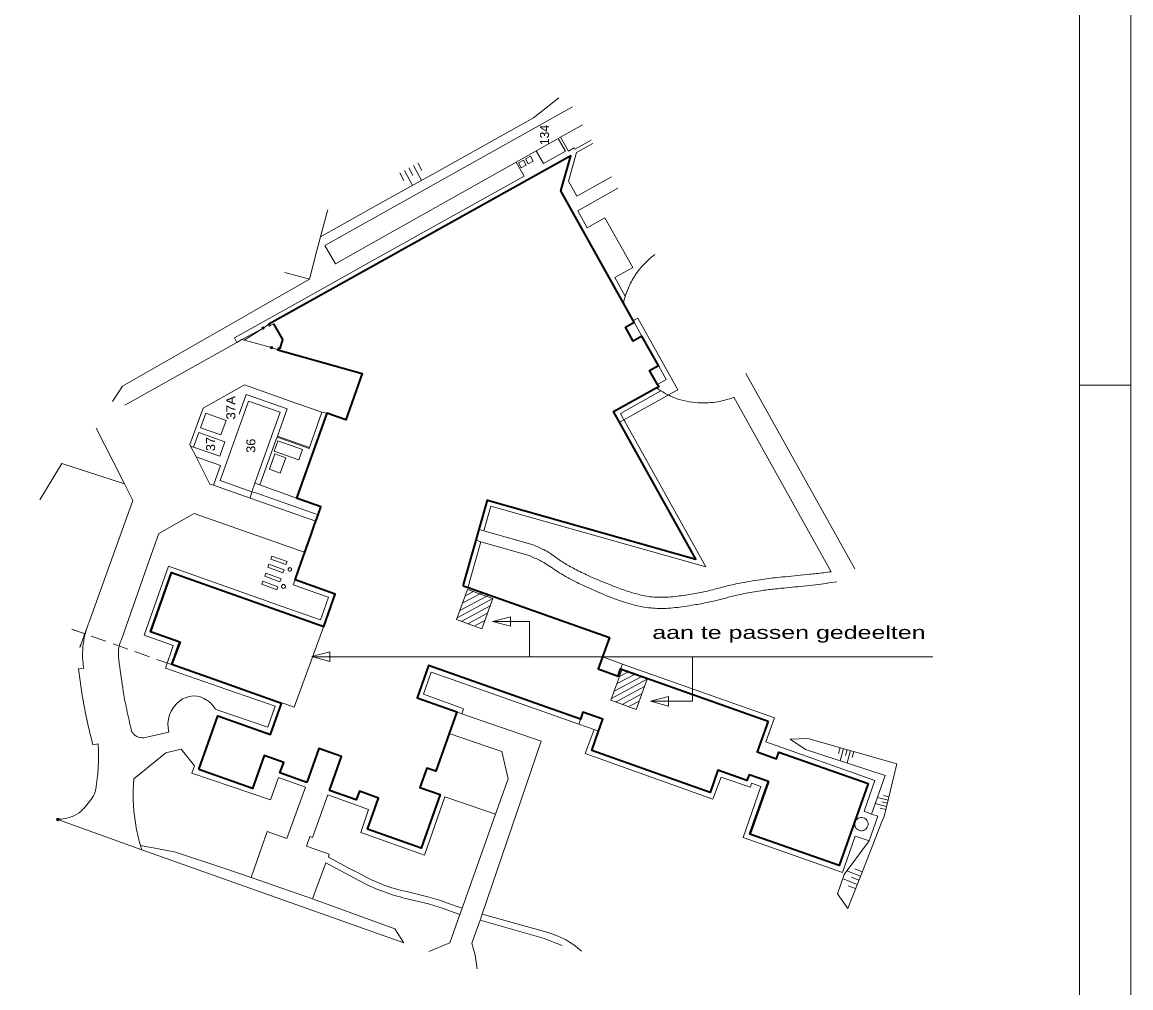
# Model space of a CAD drawing. Extents: x 295824 to 414724, y 24924 to 109024.
# Drawn here: x 393186 to 414724, y 42915 to 61673 of the extents above; entities that cross this region are included whole.
import ezdxf

# ---------------------------------------------------------------- set-up
doc = ezdxf.new("R2010")
doc.units = 0
doc.header["$LTSCALE"] = 100
doc.header["$PDMODE"] = 32
doc.header["$PDSIZE"] = 50
doc.linetypes.add('MEDIUM_DASHED', pattern=[4.5, 3, -1.5])
for name, color, linetype, lineweight in [('1', 7, 'Continuous', 13), ('16', 7, 'Continuous', 13), ('19', 7, 'Continuous', 13), ('20', 7, 'Continuous', 13), ('22', 7, 'Continuous', 13), ('25', 7, 'Continuous', 13), ('26', 7, 'Continuous', 13), ('32', 7, 'Continuous', 13), ('4', 7, 'Continuous', 35), ('40', 7, 'Continuous', 13), ('51', 7, 'Continuous', 13), ('52', 7, 'Continuous', 13), ('58', 7, 'Continuous', 35), ('62', 7, 'Continuous', 13)]:
    doc.layers.add(name, color=color, linetype=linetype, lineweight=lineweight)
doc.layers.add('57', color=7, linetype='Continuous')

msp = doc.modelspace()

# ---------------------------------------------------------------- linework, layer by layer
at = {"layer": '1'}
for p, q in [((414723.6, 24923.8), (414723.6, 109023.8)), ((413723.6, 54623.8), (414723.6, 54623.8))]:
    msp.add_line(p, q, dxfattribs=at)
msp.add_lwpolyline([(304995.6, 25923.8), (413723.6, 25923.8), (413723.6, 108023.8), (304995.6, 108023.8)], dxfattribs=at)
at = {"layer": '16'}
for p, q in [((401637.8, 50104.4), (402329.8, 50474.7)), ((401688.7, 50245), (402224.2, 50531.6)), ((401749.3, 50390.9), (402107.4, 50582.5)), ((401790.5, 50526.4), (401951.6, 50612.6)), ((401716.4, 50033.1), (402278.9, 50334.1)), ((401842.9, 49987.3), (402228, 50193.4)), ((401985.2, 49950), (402177.1, 50052.7)), ((402325.2, 50031.1), (403042.9, 50031.1)), ((403042.9, 49347.6), (403042.9, 50031.1)), ((398842.4, 49347.6), (410879.7, 49347.6)), ((404635.9, 48537.7), (405328, 48908.1)), ((404686.8, 48678.4), (405222.3, 48965)), ((404747.4, 48824.2), (405105.5, 49015.9)), ((404788.7, 48959.8), (404949.7, 49046)), ((404714.6, 48466.4), (405277, 48767.5)), ((404841, 48420.7), (405226.1, 48626.8)), ((404983.3, 48383.4), (405175.2, 48486.1))]:
    msp.add_line(p, q, dxfattribs=at)
for points in [[(401624.1, 50066.5), (402117.4, 49887.9), (402330.1, 50475.6), (401836.8, 50654.2)], [(404622.2, 48499.8), (405115.6, 48321.3), (405328.3, 48909), (404834.9, 49087.5)]]:
    msp.add_lwpolyline(points, close=True, dxfattribs=at)
msp.add_lwpolyline([(405390, 48481.1), (406207.6, 48481.1), (406207.6, 49347.6)], dxfattribs=at)
at = {"layer": '19'}
for p, q in [((397994.5, 55771.6), (398071, 55814.3)), ((398557.8, 53171.3), (398081.3, 53341.3)), ((398306.2, 53210.1), (398096.2, 53285)), ((398306.2, 53210.1), (398200.4, 52913.4)), ((398630, 53373.5), (398557.8, 53171.3)), ((398200.4, 52913.4), (397990.4, 52988.3)), ((407676.2, 48097.5), (404812.8, 49109.8))]:
    msp.add_line(p, q, dxfattribs=at)
for points in [[(403601.4, 59412.8), (403740.2, 59164.2), (403312.4, 58925.3), (403174.2, 59172.8)], [(403114.5, 58972.2), (403017.5, 58918), (402963.4, 59015), (403060.3, 59069.1)], [(402879.6, 58841), (402976.5, 58895.1), (402922.4, 58992), (402825.5, 58937.9)], [(397648.7, 52551), (397032.6, 52768.7), (397583.1, 54313.8), (398195.4, 54096.9), (397707.6, 52717.5)], [(396751.7, 54077.9), (397147.3, 53937), (397046.6, 53654.4), (396651, 53795.3)], [(397023.3, 53240.1), (397123.3, 53520.9), (396617.4, 53701.1), (396517.4, 53420.4)]]:
    msp.add_lwpolyline(points, close=True, dxfattribs=at)
for points in [[(398630, 53373.5), (398152.8, 53541.8), (398081.3, 53341.3)], [(404384.6, 47900.8), (404250.2, 47523.7), (406548.4, 46709)], [(407323.4, 45901.1), (409057.7, 45288.3), (409621.6, 46881.2)]]:
    msp.add_lwpolyline(points, dxfattribs=at)
at = {"layer": '20'}
msp.add_lwpolyline([(396651, 53795.3), (396751.7, 54077.9), (397147.3, 53937), (397046.6, 53654.4)], close=True, dxfattribs=at)
at = {"layer": '22'}
for p, q in [((397864.6, 55731.3), (397977.2, 55803.4)), ((398027.4, 55350.8), (398153.7, 55306.1)), ((398096.2, 53285), (397990.4, 52988.3))]:
    msp.add_line(p, q, dxfattribs=at)
msp.add_lwpolyline([(404790.2, 53904), (404875.3, 53951.3), (405720, 54420.6), (405739.4, 54431.4), (405921.5, 54532.6), (405147.5, 55925.7), (405057.3, 55875.6)], dxfattribs=at)
at = {"layer": '25'}
msp.add_line((409952.4, 47041.8), (409686.3, 46291.6), dxfattribs=at)
for points in [[(403610.8, 60200), (403118.7, 59814.1), (402208.5, 59305.7), (401220.8, 58754.1), (400066, 58109), (399351.9, 57710.2), (398982.8, 57504)], [(398764.9, 56679.7), (395135.1, 54600), (394939.9, 54301.2)], [(395172.3, 52704.7), (394697.8, 52857.8), (393957.3, 53096.8), (393527.8, 52393.7)], [(410181.1, 47264.9), (408451.4, 47760.6), (408105.6, 47746.2), (408403.1, 47546.5), (409952.4, 47041.8)], [(409641.4, 45769.8), (409154.8, 45117.9), (409022.6, 44737.9), (409225.8, 44458.1), (409599.6, 45406.7), (409883.1, 46125.9), (409930.4, 46245.8), (410181.1, 47264.9)]]:
    msp.add_lwpolyline(points, dxfattribs=at)
at = {"layer": '26'}
for p, q in [((400697.9, 58840.6), (400778, 58695.5)), ((400785.4, 58889), (400945, 58600)), ((400872.9, 58937.3), (400953.1, 58792.2)), ((400522.8, 58744), (400602.9, 58598.8)), ((400610.3, 58792.3), (400770.4, 58502.5)), ((409043, 47463.7), (409076.7, 47581.4)), ((409076.5, 47326.8), (409144, 47562.2)), ((409177.5, 47425.2), (409211.2, 47542.8)), ((409210.9, 47288.2), (409278.4, 47523.5)), ((409311.9, 47386.6), (409345.6, 47504.3)), ((409800.3, 46613), (410008.2, 46561.9)), ((409886.1, 46527.2), (409993.1, 46500.9)), ((409916.2, 46649.5), (410023.3, 46623.1)), ((409758, 46493.9), (409978, 46439.8)), ((409856, 46404.8), (409963, 46378.6)), ((409122.7, 45036), (409409, 44923.2)), ((409209.3, 45190.8), (409473.5, 45086.7)), ((409298.2, 45061.4), (409441.3, 45004.9)), ((409362.6, 45225), (409505.8, 45168.6)), ((409233.6, 44897.7), (409376.8, 44841.3))]:
    msp.add_line(p, q, dxfattribs=at)
at = {"layer": '32'}
for p in [(398039.3, 51301.9), (398309.4, 51135.5)]:
    msp.add_line(p, (398331.2, 51194.6), dxfattribs=at)
msp.add_lwpolyline([(398309.4, 51135.5), (398016.7, 51243.1), (398039.3, 51301.9)], dxfattribs=at)
for points in [[(397980.8, 51142.5), (397957.9, 51083.7), (398252.7, 50975.2), (398272.9, 51031.7)], [(398214.9, 50860.9), (398194.6, 50804.4), (397899.7, 50913), (397921.5, 50969.7)], [(397861.1, 50811.9), (397838.9, 50754.1), (398133.1, 50644.1), (398154.6, 50702.9)]]:
    msp.add_lwpolyline(points, close=True, dxfattribs=at)
for centre, radius, start, end in [((398414.3, 51048.8), 62.3, 174.88401, 210.92845), ((398401.9, 51024), 58.2, 110.85429, 148.54529), ((398383.6, 51038), 40.5, 38.66887, 93.52701), ((398377.3, 51045.9), 41.7, 337.95407, 24.52464), ((398386.5, 51053.6), 45, 235.11752, 280.94338), ((398381.1, 51044.4), 37.6, 291.80741, 337.95407), ((398262.2, 50712.3), 38.6, 160.33052, 203.06541), ((398262, 50712.3), 38.4, 113.54211, 160.33052), ((398262.2, 50712.3), 38.6, 203.06541, 245.79546), ((398262.6, 50712.1), 38.6, 245.06344, 293.39196), ((398262.2, 50711.8), 39, 67.13969, 113.54211), ((398262.2, 50711.8), 39, 24.60068, 67.13969), ((398262.6, 50712.1), 38.6, 293.39196, 341.72546), ((398262.8, 50712), 38.4, 341.72546, 24.60068)]:
    msp.add_arc(centre, radius, start, end, dxfattribs=at)
at = {"layer": '4', "lineweight": 13}
for p, q in [((394152.4, 49880.4), (394401.5, 49789.7)), ((394443.5, 49904.4), (394304.5, 49522.6))]:
    msp.add_line(p, q, dxfattribs=at)
at = {"layer": '4', "linetype": 'MEDIUM_DASHED', "lineweight": 13}
msp.add_line((396084.7, 49195.4), (394177.1, 49870.9), dxfattribs=at)
at = {"layer": '4'}
msp.add_line((407682.1, 46922.5), (407323.4, 45901.1), dxfattribs=at)
for points in [[(401755.5, 50725.4), (402004.7, 51607.9), (402063.4, 51815.8), (402225, 52388.3), (406270.1, 51244), (404790.2, 53904), (404676.4, 54108.5), (405505, 54568.9), (405551.2, 54594.6), (405528.8, 54634.6), (405375.9, 54908.1), (405545.3, 55002.8), (405227.1, 55571.9), (405057.8, 55477.2), (404906, 55748.7), (405075.4, 55843.3), (405057.3, 55875.6), (404867.5, 56215.2), (403647.8, 58397.1), (403847.2, 59075.1), (397977.2, 55803.4), (397994.5, 55771.6)], [(398071, 55814.3), (398242, 55507.9), (398193, 55333.5), (398163.7, 55341.7), (398153.7, 55306.1), (399789.2, 54845.9), (399472.2, 53947), (399104.7, 54076), (398516.9, 52428.8)], [(396620.6, 47155), (396988.7, 48197), (398011.6, 47835.6), (398224.4, 48439.3), (397208.2, 48799.4), (396092.4, 49194.8), (396246.1, 49628.8), (395679.9, 49831.6), (396089.4, 50984.3), (399043.4, 49934.9), (399266, 50561.5), (398487.7, 50838), (398558.6, 51047.4), (398675, 51375.3), (398791.6, 51703.9), (398866.3, 51915), (398888.5, 51977.7), (398933.2, 52104.6), (398986.9, 52261.1), (398516.9, 52428.8)], [(401755.5, 50725.4), (401848.4, 50692.5), (404592.8, 49719.5), (404459.2, 49342.8), (404378.4, 49109), (404763.5, 48970.3), (404812.8, 49109.8), (407676.2, 48097.5)], [(407840.9, 47364.6), (407885.5, 47494), (409621.6, 46881.2), (409057.7, 45288.3), (407323.4, 45901.1), (407682.1, 46922.5), (407306.7, 47054.4), (407266.2, 46939.4), (406701.7, 47141.6), (406548.4, 46709), (404250.2, 47523.7), (404384.6, 47900.8), (404467.2, 48132.8), (404078, 48271.3), (404029.4, 48133.6), (401076.5, 49176.1), (400857.1, 48550.4), (401629.1, 48277.2), (401481, 47858.5), (401220, 47121), (401046.4, 47179.6), (400911.6, 46809.4), (401307.5, 46669.3), (400938.1, 45625), (399894, 45994.6), (400109.5, 46600.3), (399736.5, 46733.1), (399676.5, 46564.6), (399153.3, 46750.8), (399387, 47407.1), (398951.8, 47561.8), (398718.4, 46905.2)], [(407676.2, 48097.5), (407463.1, 47497.9), (407840.9, 47364.6), (407885.5, 47494), (409621.6, 46881.2)], [(398718.4, 46905.2), (398194.3, 47091.4), (398266.1, 47294), (397889.1, 47427.5), (397662.3, 46786.5), (396620.6, 47155)]]:
    msp.add_lwpolyline(points, dxfattribs=at)
at = {"layer": '4', "lineweight": 13}
for centre, start, end in [((409489.7, 46095.1), 29.64, 208.17622), ((409488.7, 46097), 209.13476, 28.68146)]:
    msp.add_arc(centre, 130, start, end, dxfattribs=at)
at = {"layer": '40'}
for p, q in [((398764.9, 56679.7), (398286.4, 56808.8)), ((397864.6, 55731.3), (397454.8, 55506.7)), ((397495.8, 55495.5), (397864.6, 55731.3)), ((397495.8, 55495.5), (398027.4, 55350.8)), ((398138.2, 53614), (398145, 53632.8)), ((398766.5, 53411.1), (398145, 53632.8))]:
    msp.add_line(p, q, dxfattribs=at)
for points in [[(398764.9, 56679.7), (398911.9, 57235.7), (398982.8, 57504), (399103.3, 57960), (399121.5, 58029)], [(397454.8, 55506.7), (397495.8, 55495.5), (398027.4, 55350.8)], [(398766.5, 53411.1), (398759.8, 53392.2), (398138.2, 53614)]]:
    msp.add_lwpolyline(points, dxfattribs=at)
for p in [(397864.6, 55731.3), (398027.4, 55350.8)]:
    msp.add_point(p, dxfattribs=at)
at = {"layer": '51'}
for p, q in [((403957.9, 59142.6), (404273.2, 59318.6)), ((403799.9, 58585.5), (403957.9, 59142.6)), ((402936.5, 58681.6), (402784.5, 58953.9)), ((403962.2, 58293), (403799.9, 58585.5)), ((404636.2, 58666.8), (403962.2, 58293)), ((405047, 56907.9), (404700.3, 56714.1)), ((404903, 56351.5), (404700.3, 56714.1)), ((405075.4, 55843.3), (405227.1, 55571.9)), ((407244.8, 54850), (409362.2, 51051.9)), ((405594.3, 54510.1), (404809.2, 54069.8)), ((408900.9, 50997.6), (407012.5, 54386.6)), ((398334.9, 54159.7), (398145, 53632.8)), ((399010.6, 54094.7), (398766.5, 53411.1)), ((396517.4, 53420.4), (396458.6, 53438.4)), ((394482.1, 50007.5), (395335.4, 52381.9)), ((397612.8, 52424.6), (398888.5, 51977.7)), ((397727.4, 52532.7), (397648.7, 52551)), ((397727.4, 52532.7), (398933.2, 52104.6)), ((395837.9, 51740.3), (396526.8, 52127.6)), ((402157, 51789.4), (402291.7, 52271.2)), ((402291.7, 52271.2), (406469.1, 51093.1)), ((395553.3, 49767.1), (396029.2, 51104.4)), ((398453.6, 50744.1), (398487.7, 50838)), ((394381.4, 49123.5), (394281.5, 49111.4)), ((404848.9, 49204.6), (407802.1, 48162.4)), ((400982.3, 48621.9), (401131.9, 49048)), ((401131.9, 49048), (401542.2, 48903.6)), ((403999.3, 48038.2), (401542.2, 48903.6)), ((397957, 47975.5), (398099.6, 48385.3)), ((396037.1, 47883.5), (395551, 47773.5)), ((404295.5, 47932.6), (404121.5, 47464.7)), ((394560.4, 47633.9), (394659.7, 47657.5)), ((402123.7, 44344.8), (403266.3, 47703.7)), ((406766.5, 47010), (406661.6, 46732.2)), ((407121.4, 46884.6), (406766.5, 47010)), ((399766.3, 45934.4), (399917, 46376.6)), ((393877.2, 46186.4), (395511.3, 45595.9)), ((398706.7, 45668.9), (399149.3, 45509.8)), ((395511.3, 45595.9), (400600.1, 43786.2)), ((398823, 44643.2), (399084.9, 45339.8)), ((399084.9, 45339.8), (399837.2, 44941.7)), ((401063.5, 44682), (400650.8, 44783.7)), ((400693.3, 44640.4), (401078.9, 44544.3)), ((402123.7, 44344.8), (403381.5, 43993.6)), ((400422.4, 44061.7), (400600.1, 43786.2)), ((403305.5, 43878.6), (403676.6, 43740.2))]:
    msp.add_line(p, q, dxfattribs=at)
for points in [[(403878.2, 60027.9), (399066.9, 57331.8), (399269.8, 56979.7)], [(404073.2, 59677.8), (403645, 59437.3), (403601.4, 59412.8), (403174.2, 59172.8), (402784.5, 58953.9), (399958.2, 57366.4), (399269.8, 56979.7)], [(404238.1, 59381.5), (403923.2, 59205.7), (403910, 59229.3), (403796.5, 59165.9), (403645, 59437.3)], [(402936.5, 58681.6), (399915.1, 56994.9), (398879.3, 56416.7), (397309.5, 55540.4), (397359.4, 55453.3)], [(405047, 56907.9), (404502.1, 57871.9), (404161, 57678.1), (403977.8, 58011.1), (404759, 58446.2)], [(397454.8, 55506.7), (397359.4, 55453.3), (395179.9, 54235)], [(405528.8, 54634.6), (405698.5, 54728.7), (405545.3, 55002.8)], [(396458.6, 53438.4), (396445.5, 53466.9), (396701.9, 54177.1), (396850.4, 54259.9), (397504.7, 54624.9), (398390, 54313.2), (399010.6, 54094.7), (399104.7, 54076)], [(398334.9, 54159.7), (397538.2, 54437.2), (397403.4, 54061.5)], [(406469.1, 51093.1), (404889.6, 53925.7), (404875.3, 53951.3), (404809.2, 54069.8)], [(395335.4, 52381.9), (395172.3, 52704.7), (394960.8, 53123.1), (394624.3, 53789.1)], [(396564.7, 53229.8), (397039, 53059.1), (396902.9, 52676.3), (396833.7, 52701.2), (396564.7, 53229.8), (396458.6, 53438.4)], [(398138.2, 53614), (398116.8, 53554.6), (397802.8, 52683.6)], [(396902.9, 52676.3), (397612.8, 52424.6), (397648.7, 52551)], [(397707.6, 52717.5), (397802.8, 52683.6), (398103.7, 52576), (398198, 52542.6)], [(398198, 52542.6), (398427.2, 52460.8), (398516.9, 52428.8)], [(396526.8, 52127.6), (398576.5, 51409.8), (398675, 51375.3)], [(395837.9, 51740.3), (395660.9, 51237.6), (395106.4, 49662.6)], [(402063.4, 51815.8), (402157, 51789.4), (403113.3, 51518.6)], [(402097.2, 51581.4), (401878.4, 50799.6), (401848.4, 50692.5)], [(403008.7, 51321), (402097.2, 51581.4), (402004.7, 51607.9)], [(398982.6, 50062.5), (398682.3, 50168.4), (398347.9, 50286.4), (396029.2, 51104.4)], [(398453.6, 50744.1), (398511.3, 50723.6), (398892.3, 50588.1), (399138.3, 50500.7)], [(399138.3, 50500.7), (399046.4, 50241.9), (398982.6, 50062.5)], [(395553.3, 49767.1), (396120.9, 49567.9), (395967.6, 49127)], [(404812.8, 49109.8), (404848.9, 49204.6), (404553.5, 49310.5), (404459.2, 49342.8)], [(398099.6, 48385.3), (397165.1, 48710.4), (395967.6, 49127)], [(400982.3, 48621.9), (401622.2, 48385), (401659.3, 48371.2)], [(396940.1, 48325.3), (397026.8, 48295.5), (397957, 47975.5)], [(403266.3, 47703.7), (401730.1, 48237.9), (401759.4, 48334.1), (401659.3, 48371.2), (401622.2, 48385)], [(404029.4, 48133.6), (403999.3, 48038.2), (404295.5, 47932.6), (404384.6, 47900.8)], [(409752.5, 46942.3), (407635.3, 47691.3), (407802.1, 48162.4)], [(395355.6, 46971.7), (395978.2, 47478.2), (396272.2, 47549), (396531.4, 47225.7), (396485, 47087.4)], [(406661.6, 46732.2), (406604.8, 46581.9), (404121.5, 47464.7)], [(397124.2, 45235), (397637.2, 45061.2), (397947.5, 45954.5), (398328.1, 45813.6), (398687.2, 46815.1), (398164.9, 46998.5), (398007.6, 46564.8), (396485, 47087.4)], [(407194.1, 45836.8), (407538.1, 46828.5), (407354.8, 46892.6), (407333.1, 46811.4), (407121.4, 46884.6)], [(409752.5, 46942.3), (409541.3, 46347.8), (409686.3, 46291.6)], [(399917, 46376.6), (399122.7, 46663.4), (398827.4, 45836.6), (398773.5, 45857.7), (398706.7, 45668.9)], [(399766.3, 45934.4), (401003.4, 45492.7), (401399.4, 46622.4), (402380.3, 46289.2), (401731.5, 44464), (401427.7, 44568.5)], [(409686.3, 46291.6), (409810.6, 46247.1), (409641.4, 45769.8), (409369.2, 45859.7), (409120, 45156.7), (407194.1, 45836.8)], [(397124.2, 45235), (396148.1, 45554.6), (395485.5, 45678.6)], [(399774.9, 45116.1), (399517.2, 45247.8), (399134.7, 45454.1), (399149.3, 45509.8)], [(397637.2, 45061.2), (398823, 44643.2), (400422.4, 44061.7)], [(401413.9, 44437.9), (401689.1, 44342.5), (401492.8, 43788.4), (401087.2, 43619.9)], [(403305.5, 43878.6), (402085.5, 44227.2), (401924.6, 43784), (401983.3, 43550.4), (402022, 43282.6)]]:
    msp.add_lwpolyline(points, dxfattribs=at)
for centre, radius, start, end in [((406410.8, 55885.5), 1578.2, 126.29056, 137.1502), ((406406.2, 55879.2), 1579, 136.86919, 144.86761), ((406413.8, 55891.4), 1577.5, 148.248, 158.08467), ((406423.8, 55906.6), 1578, 146.04811, 148.90934), ((406405.8, 55871.7), 1577.5, 157.31277, 162.2913), ((406410.8, 55885.5), 1578.2, 162.82504, 167.93957), ((406427.5, 55873.2), 1597.5, 234.73007, 238.56524), ((406427.5, 55873.2), 1597.5, 238.56524, 244.48705), ((406471.1, 55857.9), 1603.2, 242.84296, 249.97212), ((406398.7, 55877.4), 1598.5, 252.65339, 269.25839), ((406440.6, 55874), 1596.1, 267.75368, 272.9189), ((406440.6, 55874), 1596.1, 272.9189, 279.38393), ((406427.5, 55873.2), 1597.5, 279.85146, 291.48171), ((401965, 48682), 3060.2, 63.73678, 67.96053), ((401291.5, 47136.2), 4523.4, 64.74941, 67.69024), ((402878.4, 50533.1), 996, 56.32959, 63.73678), ((400533.4, 47013), 5225.7, 53.87718, 56.32959), ((402781, 50294.1), 1031.8, 58.58977, 64.74941), ((400079.4, 45870), 6215.6, 55.7123, 58.58977), ((404376.7, 52279.1), 1293.7, 233.87718, 238.80723), ((405884.9, 54770.1), 4205.8, 238.80723, 242.2048), ((406481.1, 55901.1), 5484.2, 242.2048, 245.18002), ((404872.1, 52899.1), 2291.9, 235.7123, 240.45176), ((405325.3, 53698.5), 3210.9, 240.45176, 244.44182), ((406378.7, 55679.8), 5240.4, 245.18002, 247.51654), ((410108.8, 64692.5), 14994.5, 247.51654, 248.89777), ((409309.8, 39421.5), 11561, 99.10473, 101.27121), ((408549.6, 44164.7), 6757.2, 96.27081, 99.10473), ((409190, 38337.4), 12619.6, 95.37354, 96.27081), ((400951, 125928.1), 75357.8, 275.37354, 275.74072), ((407837.8, 57424), 6508.4, 275.74072, 276.81483), ((404156.2, 88231), 37534.6, 276.81483, 277.26209), ((410665.3, 64865), 15588.6, 244.44183, 244.94759), ((410665.3, 64865), 15588.6, 244.94759, 246.25241), ((406350.5, 54953.8), 4555.8, 248.89777, 252.38967), ((405062.6, 56855.5), 6395.7, 282.34377, 284.86156), ((405062.6, 56855.5), 6395.7, 284.86156, 285.60827), ((407758.5, 47205.1), 3624.2, 101.27121, 105.60827), ((409131.5, 40246.2), 10503, 98.75261, 100.55259), ((408513.3, 44261.4), 6440.6, 96.45394, 98.75261), ((408601.9, 43477.6), 7229.3, 95.37081, 96.45394), ((400911.9, 125274.7), 74928.4, 275.37081, 275.70725), ((407559.9, 58755.3), 8077.7, 275.70725, 277.36407), ((405254.2, 76595.7), 26066.5, 277.36407, 278.28636), ((406644.1, 55725.1), 5603.1, 246.25241, 251.30735), ((405762.3, 53118.8), 2851.8, 251.30735, 258.39517), ((406100.4, 54165.8), 3729.1, 252.38968, 256.2494), ((405562.6, 51968), 1466.4, 256.2494, 267.13568), ((405598.1, 52677.6), 2176.9, 267.13568, 276.06602), ((405139.6, 56992.1), 6515.7, 276.06602, 278.95687), ((405414.9, 55245.2), 4747.3, 278.95687, 282.34377), ((405323.8, 55926.6), 5648.3, 279.28211, 282.17072), ((404947, 57673.2), 7435.1, 282.17071, 285.46087), ((407820, 47286.1), 3342, 100.55259, 105.46087), ((405598.2, 52319.5), 2035.8, 258.39517, 267.88214), ((405603.6, 52466.9), 2183.2, 267.88214, 277.04242), ((404719.5, 59623.8), 9394.5, 277.04242, 279.28211), ((395978.7, 49390.6), 1618.7, 157.59913, 166.33894), ((395985.4, 49388.4), 1625.8, 166.31962, 175.05942), ((395331, 49477.4), 271.9, 165.51022, 179.4869), ((395984, 49308.6), 946.3, 158.03226, 165.51022), ((395987, 49388.4), 1627.4, 175.06279, 182.21363), ((395987.8, 49388.6), 1628.2, 182.22234, 189.37318), ((399537, 49439.7), 4478, 179.4869, 181.36323), ((395932.7, 49353.9), 872.7, 181.36323, 185.61426), ((404533.7, 50284.4), 10319.1, 186.52713, 188.62019), ((396289.9, 49389), 1231.6, 185.61426, 188.32056), ((500071.8, 64567.2), 106117.5, 188.32056, 188.61209), ((404578.6, 50290.4), 10364.4, 188.61557, 190.70863), ((400563.9, 49496.6), 5474.9, 188.61209, 191.8452), ((396584.6, 48032), 567.3, 127.0737, 195.1798), ((396520, 48148.9), 435.4, 53.34093, 129.55669), ((396508.5, 48086.4), 493.3, 28.9771, 56.61769), ((404579.1, 50290.5), 10364.9, 190.70868, 192.77844), ((408927.7, 51250.8), 14020.7, 191.8452, 193.56084), ((404593.2, 50293.9), 10379.4, 192.77998, 194.84974), ((408927.7, 51250.8), 14020.7, 193.56084, 193.86537), ((395517.8, 48007.4), 233.4, 209.96911, 223.92548), ((395517.8, 48007.4), 233.4, 223.92548, 237.88186), ((390536.2, 47337), 4135.9, 1.68739, 4.44382), ((395517.8, 48007.4), 233.4, 237.88186, 256.92832), ((395527.6, 48033.2), 260.8, 256.10746, 275.15393), ((392785.5, 47402.7), 1885.7, 357.60767, 1.70362), ((388657.9, 47576.5), 6016.9, 354.34626, 357.59535), ((392284.9, 47216.6), 2372.1, 349.17636, 354.36574), ((398789, 46663.7), 3447.3, 174.87442, 175.30239), ((394174.3, 46854.7), 448.3, 325.95767, 349.25694), ((398789, 46663.7), 3447.3, 175.30239, 180.57924), ((393276.3, 47463.6), 1533.4, 313.37054, 325.89), ((398789, 46663.7), 3447.3, 180.57924, 185.24038), ((394005.9, 46690.1), 470, 288.46567, 313.47185), ((398789, 46663.7), 3447.3, 185.24038, 191.42851), ((393834, 47088.8), 903.4, 272.74207, 290.80053), ((398789, 46663.7), 3447.3, 191.42851, 196.60432), ((398789, 46663.7), 3447.3, 196.60433, 198.04367), ((401351.6, 47950.8), 3243.7, 240.91681, 257.52249), ((401462.4, 48192.8), 3634.7, 243.43983, 257.7842), ((400521, 42299.8), 2443.2, 68.21629, 77.1705), ((400109.9, 40911.3), 3760, 69.70629, 75.06476), ((402989.7, 42485.7), 1558, 47.15378, 75.43561)]:
    msp.add_arc(centre, radius, start, end, dxfattribs=at)
msp.add_point((393877.2, 46186.4), dxfattribs=at)
at = {"layer": '52'}
for p, q in [((401730.1, 48237.9), (401629.1, 48277.2)), ((401731.5, 44464), (401689.1, 44342.5)), ((402123.7, 44344.8), (402085.5, 44227.2))]:
    msp.add_line(p, q, dxfattribs=at)
msp.add_lwpolyline([(401481, 47858.5), (402502.3, 47505.7), (402624.1, 46973), (402380.3, 46289.2)], dxfattribs=at)
at = {"layer": '58'}
msp.add_line((394312.9, 49562.2), (394326.5, 49568.5), dxfattribs=at)
at = {"layer": '62'}
for points in [[(395691.1, 49831.8), (396094.1, 50968.7), (399048.7, 49937.2), (398469.3, 48369.3), (396105.9, 49199.4), (396270.5, 49627.6)], [(402325.2, 50031.1), (402674.2, 50124.6), (402674.2, 49937.6)], [(398810.8, 49347.8), (399159.7, 49441.3), (399159.7, 49254.3)], [(405390, 48481.1), (405739, 48574.6), (405739, 48387.6)]]:
    msp.add_lwpolyline(points, close=True, dxfattribs=at)

# ---------------------------------------------------------------- texts
at = {"layer": '16', "width": 1.45}
msp.add_text('aan te passen gedeelten', height=250, dxfattribs=at).set_placement((405426.9, 49693.9))
at = {"layer": '57'}
msp.add_text('134', height=175, rotation=90, dxfattribs=at).set_placement((403420.3, 59285.5))
for s, width, p in [('37A', 1.1, (397327.6, 53953.2)), ('37', 1.05, (396934, 53339.7)), ('36', 1.05, (397716.2, 53307.9))]:
    msp.add_text(s, height=175, rotation=90, dxfattribs=dict(at, width=width)).set_placement(p)

doc.saveas('drawing.dxf')
